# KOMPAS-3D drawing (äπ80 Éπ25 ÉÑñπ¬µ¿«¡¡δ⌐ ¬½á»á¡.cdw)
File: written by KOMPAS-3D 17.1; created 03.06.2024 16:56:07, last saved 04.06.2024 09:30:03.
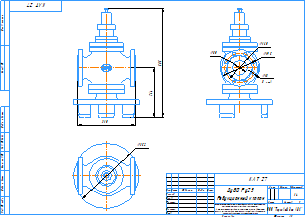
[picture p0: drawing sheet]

Sheet 1: A3, landscape

Title block, sheet 1: name: Ду80 Ру25 / Редукционный клапан; designation: КАТ 27; material: Внимание! Данный продукт является объектом авторского права ООО «Торговый Дом АДЛ». / Запрещается изменение, копирование, распространение / (в том числе путем копирования на другие сайты и ресурсы в Интернете) / или любое иное использование информации и объектов без предварительного / согласия правообладателя (ООО «Торговый Дом АДЛ»).; sheets: 1; organisation: ООО "Торговый дом АДЛ"; sheet format: A3; stored path: C:\Users\klav\Desktop\Модели\КАТ 27\KOMPAS 3D\Чертеж.cdw

Views: Вид 1, Спереди, Проекционный вид 2, Проекционный вид 3
Referenced files in C:\Users\klav\Desktop\Модели\КАТ 27\KOMPAS 3D\: КАТ27_ Ду65 Ру25 Редукционный клапан.m3d, КАТ27_Ду80 Ру25 Редукционный клапан.m3d
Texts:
  Клочков АВ
  ООО АДЛ Групп
  КАТ27_
Dimensions and other numbers on the sheet: 310; 264; 585; 160; 195; 80; 18; 8 отв.; 352; 1:4; 1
